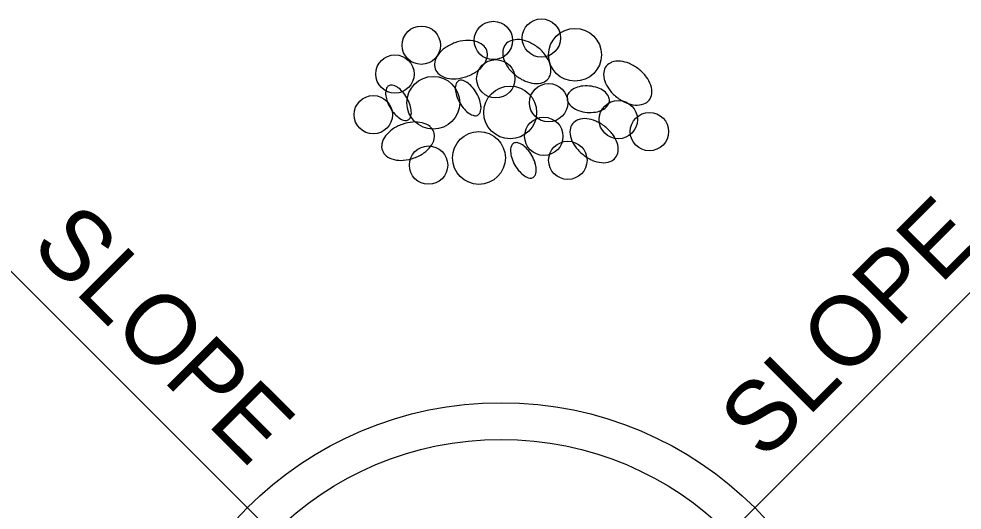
# Model space of a CAD drawing. Extents: x 9962.8 to 10024.8, y 9905.2 to 10002.8.
# Drawn here: x 9976.35 to 9990.41, y 9995.42 to 10002.75 of the extents above; entities that cross this region are included whole.
import ezdxf

# ---------------------------------------------------------------- set-up
doc = ezdxf.new("R2010")
doc.units = 0
for name, color, linetype in [('G-ANNO-TEXT', 7, 'Continuous'), ('G-DETL-LINE', 7, 'Continuous'), ('G-DETL-PATT', 7, 'Continuous')]:
    doc.layers.add(name, color=color, linetype=linetype)

msp = doc.modelspace()

# ---------------------------------------------------------------- linework, layer by layer
at = {"layer": 'G-ANNO-TEXT'}
for p, q in [((9982.487, 9992.728), (9975.059, 10000.157)), ((9984.589, 9992.728), (9992.017, 10000.157))]:
    msp.add_line(p, q, dxfattribs=at)
at = {"layer": 'G-DETL-LINE'}
for radius in [5.348, 4.8]:
    msp.add_circle((9983.538, 9991.678), radius, dxfattribs=at)
at = {"layer": 'G-DETL-PATT'}
for centre, radius in [((9983.423, 10002.432), 0.286), ((9984.139, 10002.468), 0.286), ((9982.348, 10002.361), 0.286), ((9984.64, 10002.218), 0.394), ((9981.955, 10001.931), 0.286), ((9983.459, 10001.86), 0.286), ((9982.527, 10001.502), 0.394), ((9983.673, 10001.358), 0.394), ((9984.246, 10001.502), 0.286), ((9981.632, 10001.323), 0.286), ((9985.285, 10001.251), 0.286), ((9984.175, 10001.001), 0.286), ((9985.75, 10001.072), 0.286), ((9983.208, 10000.678), 0.394), ((9982.456, 10000.571), 0.286), ((9984.533, 10000.643), 0.286)]:
    msp.add_circle(centre, radius, dxfattribs=at)
for centre, radius, start, end in [((9983.06, 10001.808), 0.625, 109.6611, 124.758), ((9983.06, 10001.808), 0.625, 94.5642, 109.6611), ((9983.046, 10001.991), 0.442, 76.5864, 94.5642), ((9983.076, 10002.12), 0.309, 52.1181, 76.5864), ((9983.741, 10002.261), 0.177, 109.2198, 141.6767), ((9983.784, 10002.137), 0.309, 84.7515, 109.2198), ((9983.772, 10002.004), 0.442, 66.7736, 84.7515), ((9983.7, 10001.836), 0.625, 51.6767, 66.7736), ((9982.956, 10001.958), 0.442, 124.758, 142.7358), ((9983.157, 10002.224), 0.177, 19.6611, 52.1181), ((9983.157, 10002.224), 0.177, 347.2041, 19.6611), ((9983.871, 10002.247), 0.309, 174.1337, 198.602), ((9983.741, 10002.261), 0.177, 141.6767, 174.1337), ((9983.7, 10001.836), 0.625, 36.5799, 51.6767), ((9982.849, 10002.039), 0.309, 142.7358, 167.2041), ((9983.029, 10002.253), 0.309, 322.7358, 347.2041), ((9983.998, 10002.29), 0.442, 198.602, 216.5799), ((9983.847, 10001.945), 0.442, 18.602, 36.5799), ((9985.288, 10001.815), 0.309, 84.7515, 109.2198), ((9985.276, 10001.682), 0.442, 66.7736, 84.7515), ((9982.722, 10002.068), 0.177, 167.2041, 199.6611), ((9982.722, 10002.068), 0.177, 199.6611, 232.1181), ((9982.923, 10002.334), 0.442, 304.758, 322.7358), ((9984.145, 10002.399), 0.625, 216.5798, 231.6767), ((9983.973, 10001.987), 0.309, 354.1337, 18.602), ((9985.245, 10001.938), 0.177, 141.6767, 174.1337), ((9985.245, 10001.938), 0.177, 109.2198, 141.6767), ((9985.204, 10001.513), 0.625, 51.6767, 66.7736), ((9985.204, 10001.513), 0.625, 36.5799, 51.6767), ((9982.802, 10002.172), 0.309, 232.1181, 256.5864), ((9982.833, 10002.301), 0.442, 256.5864, 274.5642), ((9982.818, 10002.484), 0.625, 274.5642, 289.6611), ((9982.939, 10001.763), 0.0756, 79.6177, 119.7352), ((9982.914, 10001.63), 0.211, 55.9134, 79.6177), ((9982.818, 10002.484), 0.625, 289.6611, 304.758), ((9984.145, 10002.399), 0.625, 231.6767, 246.7736), ((9984.104, 10001.974), 0.177, 289.2198, 321.6767), ((9984.104, 10001.974), 0.177, 321.6767, 354.1337), ((9985.375, 10001.925), 0.309, 174.1337, 198.602), ((9985.351, 10001.623), 0.442, 18.602, 36.5799), ((9982.027, 10001.644), 0.211, 159.8528, 183.557), ((9981.9, 10001.691), 0.0756, 119.7352, 159.8528), ((9981.9, 10001.691), 0.0756, 79.6177, 119.7352), ((9981.876, 10001.558), 0.211, 55.9134, 79.6177), ((9981.788, 10001.428), 0.367, 41.2446, 55.9134), ((9983.066, 10001.716), 0.211, 159.8528, 183.557), ((9983.222, 10001.726), 0.367, 183.557, 198.2258), ((9982.939, 10001.763), 0.0756, 119.7352, 159.8528), ((9982.826, 10001.5), 0.367, 41.2446, 55.9134), ((9982.655, 10001.349), 0.596, 29.7352, 41.2446), ((9984.073, 10002.231), 0.442, 246.7736, 264.7515), ((9984.06, 10002.098), 0.309, 264.7515, 289.2198), ((9984.733, 10001.504), 0.236, 116.7392, 141.1979), ((9984.784, 10001.403), 0.349, 99.2802, 116.7392), ((9984.809, 10001.247), 0.507, 84.8036, 99.2802), ((9984.809, 10001.247), 0.507, 70.3269, 84.8036), ((9984.862, 10001.396), 0.349, 52.8679, 70.3269), ((9985.502, 10001.968), 0.442, 198.602, 216.5799), ((9985.649, 10002.077), 0.625, 216.5798, 231.6767), ((9985.477, 10001.665), 0.309, 354.1337, 18.602), ((9982.183, 10001.654), 0.367, 183.557, 198.2258), ((9981.616, 10001.278), 0.596, 29.7352, 41.2446), ((9981.616, 10001.278), 0.596, 18.2258, 29.7352), ((9983.439, 10001.797), 0.596, 198.2258, 209.7352), ((9982.655, 10001.349), 0.596, 18.2258, 29.7352), ((9984.648, 10001.573), 0.127, 141.1979, 174.8035), ((9984.648, 10001.573), 0.127, 174.8036, 208.4092), ((9984.931, 10001.486), 0.236, 28.4092, 52.8679), ((9985.027, 10001.538), 0.127, 354.8036, 28.4092), ((9985.649, 10002.077), 0.625, 231.6767, 246.7736), ((9985.608, 10001.652), 0.177, 321.6767, 354.1337), ((9982.4, 10001.725), 0.596, 198.2258, 209.7352), ((9982.4, 10001.725), 0.596, 209.7352, 221.2446), ((9981.833, 10001.349), 0.367, 3.557, 18.2258), ((9983.439, 10001.797), 0.596, 209.7352, 221.2446), ((9982.872, 10001.421), 0.367, 3.557, 18.2258), ((9983.028, 10001.431), 0.211, 339.8528, 3.557), ((9984.744, 10001.625), 0.236, 208.4092, 232.8679), ((9984.812, 10001.715), 0.349, 232.8679, 250.3269), ((9984.942, 10001.607), 0.236, 296.7392, 321.1979), ((9985.027, 10001.538), 0.127, 321.1979, 354.8035), ((9985.577, 10001.908), 0.442, 246.7736, 264.7515), ((9985.564, 10001.776), 0.309, 264.7515, 289.2198), ((9985.608, 10001.652), 0.177, 289.2198, 321.6767), ((9982.229, 10001.575), 0.367, 221.2446, 235.9134), ((9982.116, 10001.312), 0.0756, 299.7352, 339.8528), ((9981.989, 10001.359), 0.211, 339.8528, 3.557), ((9983.267, 10001.647), 0.367, 221.2446, 235.9134), ((9983.179, 10001.517), 0.211, 235.9134, 259.6177), ((9983.155, 10001.384), 0.0756, 259.6177, 299.7352), ((9983.155, 10001.384), 0.0756, 299.7352, 339.8528), ((9984.865, 10001.864), 0.507, 250.3269, 264.8036), ((9984.865, 10001.864), 0.507, 264.8036, 279.2802), ((9984.891, 10001.708), 0.349, 279.2802, 296.7392), ((9982.272, 10000.591), 0.625, 109.6611, 124.758), ((9982.141, 10001.445), 0.211, 235.9134, 259.6177), ((9982.272, 10000.591), 0.625, 94.5642, 109.6611), ((9982.116, 10001.312), 0.0756, 259.6177, 299.7352), ((9982.258, 10000.773), 0.442, 76.5864, 94.5642), ((9982.289, 10000.903), 0.309, 52.1181, 76.5864), ((9982.369, 10001.007), 0.177, 19.6611, 52.1181), ((9984.743, 10001.079), 0.177, 141.6767, 174.1337), ((9984.743, 10001.079), 0.177, 109.2198, 141.6767), ((9984.787, 10000.956), 0.309, 84.7515, 109.2198), ((9984.774, 10000.823), 0.442, 66.7736, 84.7515), ((9984.702, 10000.654), 0.625, 51.6767, 66.7736), ((9984.702, 10000.654), 0.625, 36.5799, 51.6767), ((9982.062, 10000.822), 0.309, 142.7358, 167.2041), ((9982.168, 10000.741), 0.442, 124.758, 142.7358), ((9982.369, 10001.007), 0.177, 347.2041, 19.6611), ((9984.874, 10001.066), 0.309, 174.1337, 198.602), ((9984.849, 10000.764), 0.442, 18.602, 36.5799), ((9981.934, 10000.851), 0.177, 167.2041, 199.6611), ((9982.135, 10001.117), 0.442, 304.758, 322.7358), ((9982.241, 10001.036), 0.309, 322.7358, 347.2041), ((9983.889, 10000.785), 0.211, 159.8528, 183.557), ((9983.762, 10000.832), 0.0756, 119.7352, 159.8528), ((9983.762, 10000.832), 0.0756, 79.6177, 119.7352), ((9983.738, 10000.699), 0.211, 55.9134, 79.6177), ((9983.65, 10000.569), 0.367, 41.2446, 55.9134), ((9985, 10001.109), 0.442, 198.602, 216.5799), ((9984.976, 10000.806), 0.309, 354.1337, 18.602), ((9981.934, 10000.851), 0.177, 199.6611, 232.1181), ((9982.014, 10000.955), 0.309, 232.1181, 256.5864), ((9982.031, 10001.267), 0.625, 289.6611, 304.758), ((9984.045, 10000.795), 0.367, 183.557, 198.2258), ((9983.479, 10000.419), 0.596, 29.7352, 41.2446), ((9983.479, 10000.419), 0.596, 18.2258, 29.7352), ((9985.148, 10001.218), 0.625, 216.5798, 231.6767), ((9985.148, 10001.218), 0.625, 231.6767, 246.7736), ((9985.106, 10000.793), 0.177, 321.6767, 354.1337), ((9982.045, 10001.084), 0.442, 256.5864, 274.5642), ((9982.031, 10001.267), 0.625, 274.5642, 289.6611), ((9984.262, 10000.866), 0.596, 198.2258, 209.7352), ((9984.262, 10000.866), 0.596, 209.7352, 221.2446), ((9983.695, 10000.49), 0.367, 3.557, 18.2258), ((9985.075, 10001.049), 0.442, 246.7736, 264.7515), ((9985.063, 10000.916), 0.309, 264.7515, 289.2198), ((9985.106, 10000.793), 0.177, 289.2198, 321.6767), ((9984.091, 10000.716), 0.367, 221.2446, 235.9134), ((9983.978, 10000.453), 0.0756, 299.7352, 339.8528), ((9983.852, 10000.5), 0.211, 339.8528, 3.557), ((9984.003, 10000.586), 0.211, 235.9134, 259.6177), ((9983.978, 10000.453), 0.0756, 259.6177, 299.7352)]:
    msp.add_arc(centre, radius, start, end, dxfattribs=at)

# ---------------------------------------------------------------- texts
at = {"layer": 'G-ANNO-TEXT'}
for rotation, p in [(45, (9987.454, 9996.145)), (315, (9976.502, 9999.339))]:
    msp.add_text('SLOPE', height=1.044, rotation=rotation, dxfattribs=at).set_placement(p)

doc.saveas('drawing.dxf')
